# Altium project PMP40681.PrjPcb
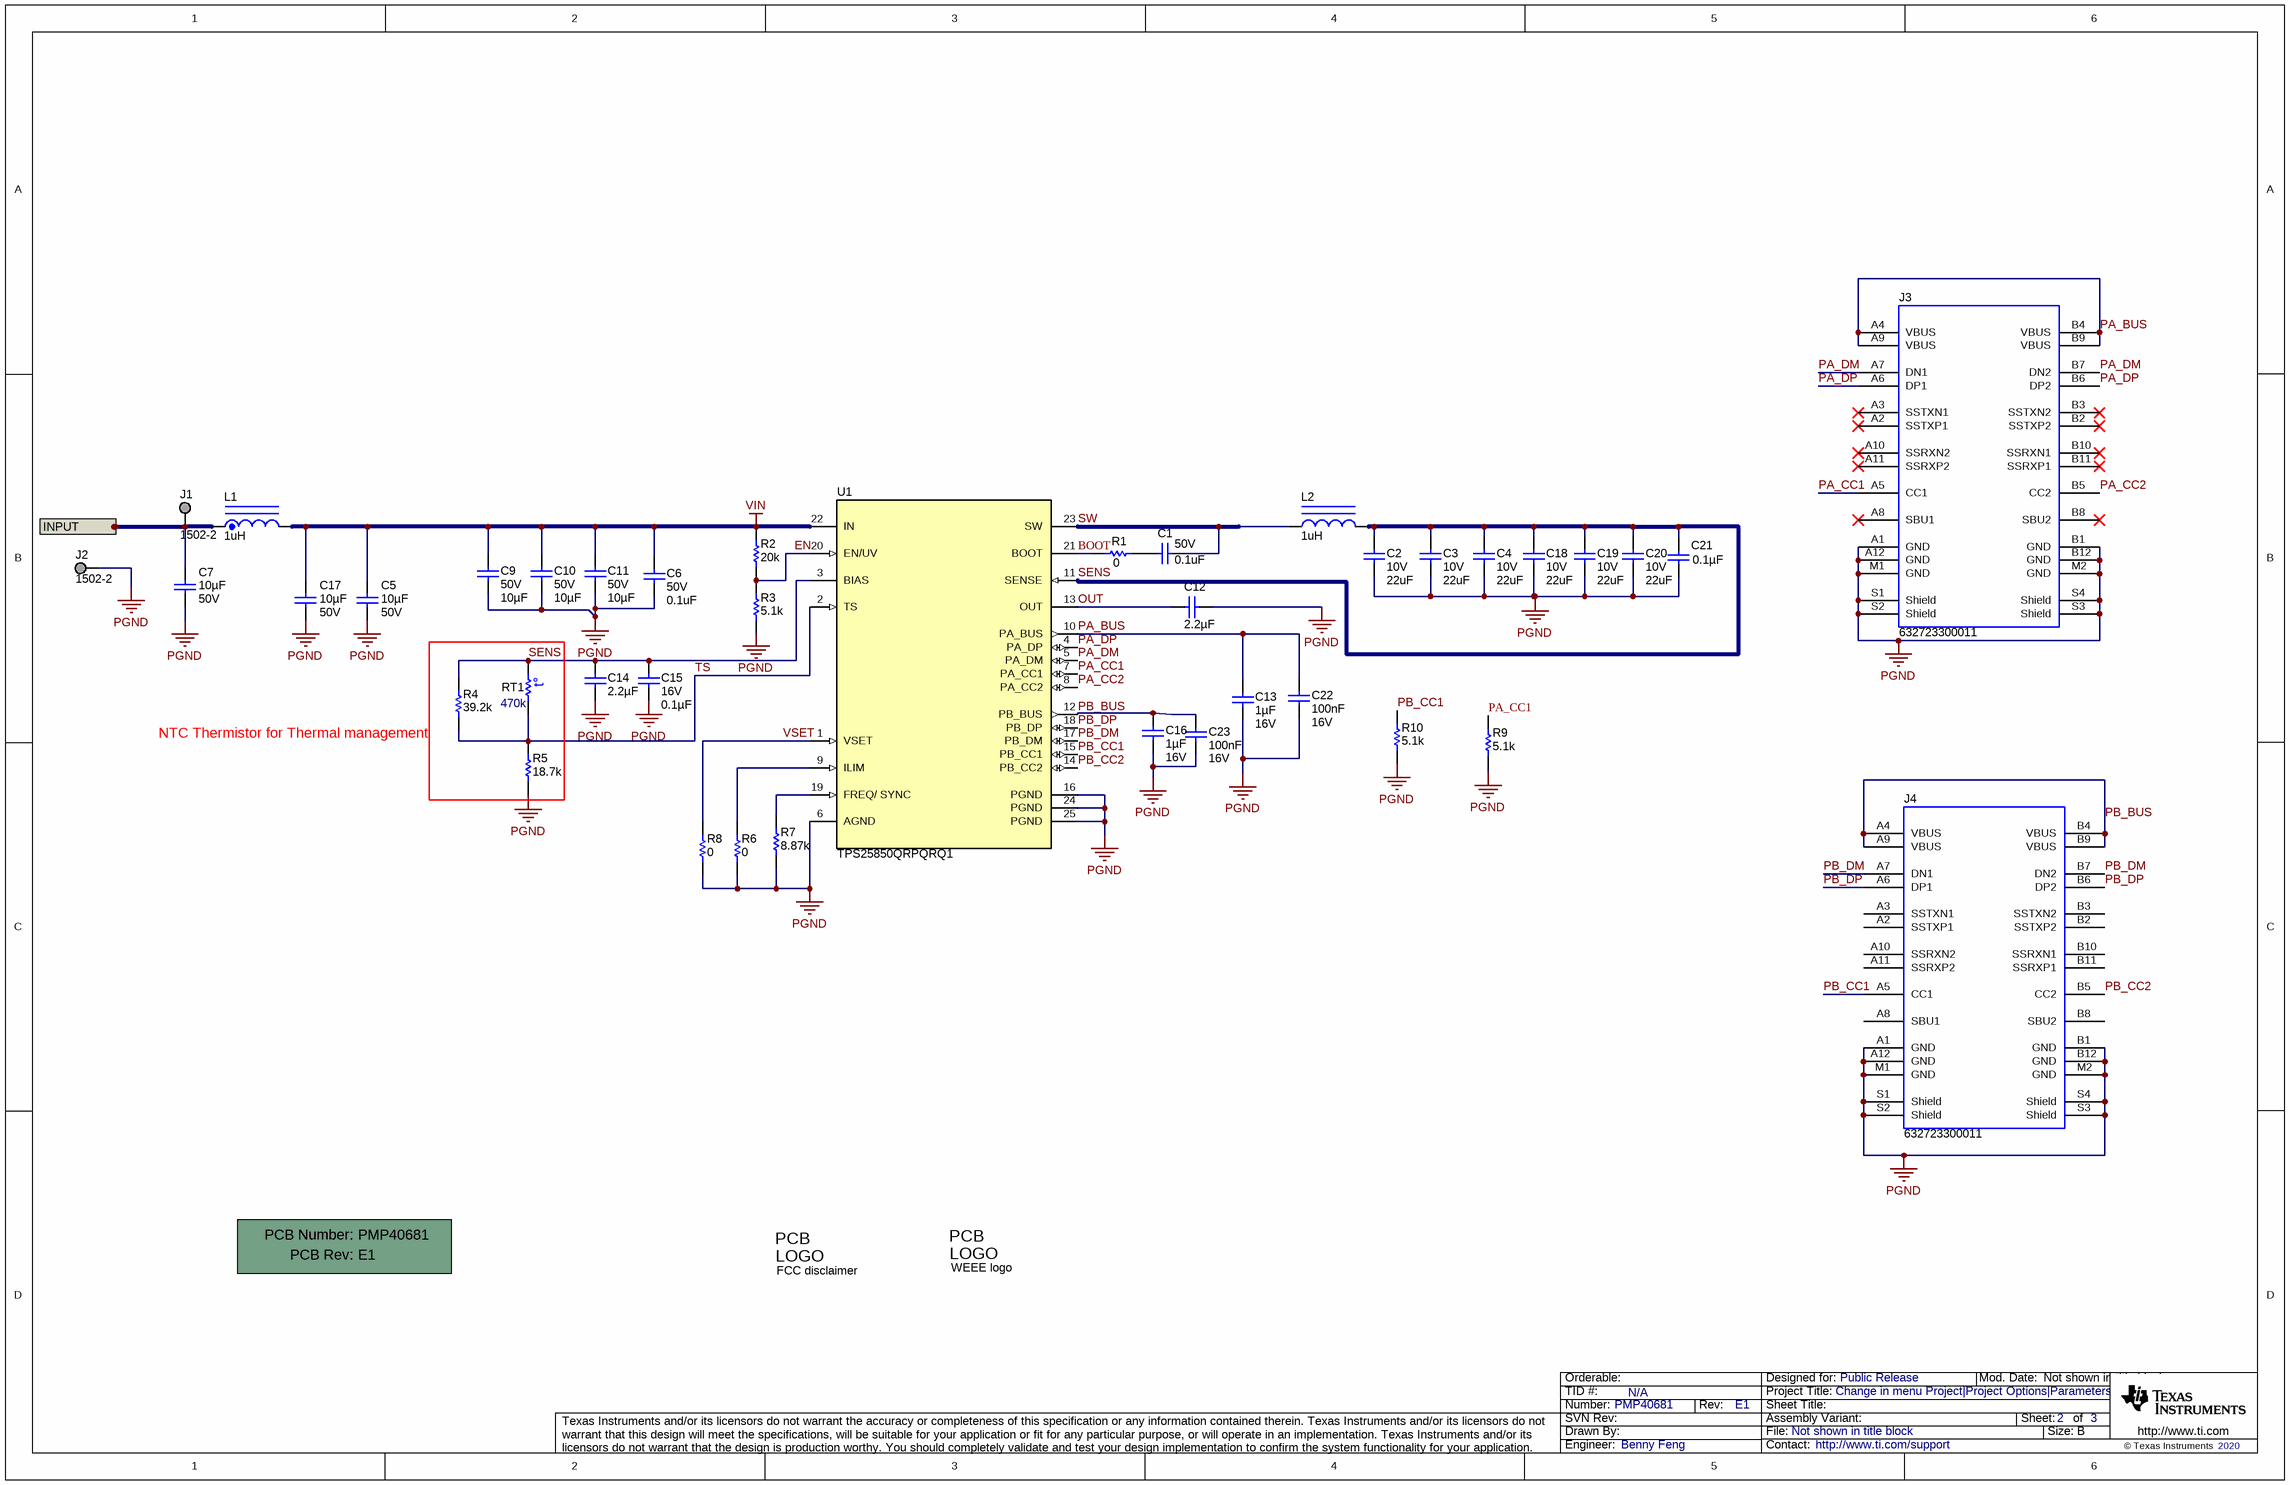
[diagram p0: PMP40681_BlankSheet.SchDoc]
CopyrightYear: 2020; PCB_Layout: Benny Feng; PCB_Rev: E1; PRJ_Customer: Public Release; PRJ_Engineer: Benny Feng; PRJ_Number: PMP40681; PRJ_Title: Change in menu Project|Project Options|Parameters; SCH_Rev: E1; TechSupport: http://www.ti.com/support; TID: N/A
1 sheet, 43 parts. Net scope: flat (ports and power ports of the same name join across sheets).
Board file: PMP40681_PCB.PcbDoc

## Sheet PMP40681_BlankSheet.SchDoc
size 431 x 279 mm; Date: Not shown in title block; ApprovedBy: Not shown in title block; CheckedBy: Not shown in title block; Author: Not shown in title block; CompanyName: Not shown in title block; Engineer: Not shown in title block; Organization: Not shown in title block; Address1: Not shown in title block; Address2: Not shown in title block; Address3: Not shown in title block; Address4: Not shown in title block; DocumentNumber: 2; Revision: Use project parameter SCH_Rev; SheetNumber: 2; SheetTotal: 3; PageSetup: Record=PageOptions¦CenterHorizontal=True¦CenterVertical=True¦PrintScale=1.00¦XCorrection=1.00¦YCorrection=1.00¦PrintKind=0¦BorderSize=5000000¦LeftOffset=0¦BottomOffset=0¦Orientation=2¦PaperLength=1000¦PaperWidth=1000¦Scale=100¦PaperSource=15¦PrintQuality=600¦MediaType=1¦DitherType=10¦PaperKind=Letter¦PrintScaleMode=1

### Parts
!PCB1  Printed Circuit Board  (value not drawn)  (mechanical)
C1  VDC_V: 50V  ValueDisplayed: 0.1uF  [0402]  (hidden comment: GCM155R71H104KE02D)
C2  VDC_V: 10V  ValueDisplayed: 22uF  [1206_180]  (hidden comment: GCM31CR71A226KE02)
C3  VDC_V: 10V  ValueDisplayed: 22uF  [1206_180]  (hidden comment: GCM31CR71A226KE02)
C4  VDC_V: 10V  ValueDisplayed: 22uF  [1206_180]  (hidden comment: GCM31CR71A226KE02)
C5  ValueDisplayed: 10µF  VDC_V: 50V  [1206_190]  (hidden comment: CGA5L1X7R1H106K160AC)
C6  VDC_V: 50V  ValueDisplayed: 0.1uF  [0402]  (hidden comment: GCM155R71H104KE02D)
C7  ValueDisplayed: 10µF  VDC_V: 50V  [1206_190]  (hidden comment: CGA5L1X7R1H106K160AC)
C9  VDC_V: 50V  ValueDisplayed: 10µF  [1206_190]  (hidden comment: CGA5L1X7R1H106K160AC)
C10  VDC_V: 50V  ValueDisplayed: 10µF  [1206_190]  (hidden comment: CGA5L1X7R1H106K160AC)
C11  VDC_V: 50V  ValueDisplayed: 10µF  [1206_190]  (hidden comment: CGA5L1X7R1H106K160AC)
C12  Cap_F: 2.2µF  [0603]  (hidden comment: GRM188R71A225KE15J)
C13  Cap_F: 1µF  VDC_V: 16V  [0603]  (hidden comment: GCM188R71C105KA64D)
C14  Cap_F: 2.2µF  [0603]  (hidden comment: GRM188R71A225KE15J)
C15  VDC_V: 16V  ValueDisplayed: 0.1µF  [0402]  (hidden comment: GCM155R71C104JA55D)
C16  Cap_F: 1µF  VDC_V: 16V  [0603]  (hidden comment: GCM188R71C105KA64D)
C17  ValueDisplayed: 10µF  VDC_V: 50V  [1206_190]  (hidden comment: CGA5L1X7R1H106K160AC)
C18  VDC_V: 10V  ValueDisplayed: 22uF  [1206_180]  (hidden comment: GCM31CR71A226KE02)
C19  VDC_V: 10V  ValueDisplayed: 22uF  [1206_180]  (hidden comment: GCM31CR71A226KE02)
C20  VDC_V: 10V  ValueDisplayed: 22uF  [1206_180]  (hidden comment: GCM31CR71A226KE02)
C21  ValueDisplayed: 0.1µF  [0603]  (hidden comment: C0603C104K5RACAUTO)
C22  Cap_F: 100nF  VDC_V: 16V  [0603]  (hidden comment: GCM188R71C104KA37J)
C23  Cap_F: 100nF  VDC_V: 16V  [0603]  (hidden comment: GCM188R71C104KA37J)
J1  1502-2  [Keystone1502-2]
J2  1502-2  [Keystone1502-2]
J3  632723300011  [Wurth_632_723_300_011]
J4  632723300011  [Wurth_632_723_300_011]
L1  ValueDisplayed: 1uH  [XAL4020]  (hidden comment: XAL4020-102MEB)
L2  ValueDisplayed: 1uH  [XAL8080]  (hidden comment: XAL8080-102MEB)
Logo1  FCC disclaimer  [FCC_disclaimer]  (no BOM)
Logo2  WEEE logo  [WEEE_Minimum]  (no BOM)
R1  ValueDisplayed: 0  [0402]  (hidden comment: CRCW04020000Z0ED)
R2  ValueDisplayed: 20k  [0402]  (hidden comment: CRCW040220K0JNED)
R3  ValueDisplayed: 5.1k  [0402]  (hidden comment: CRCW04025K10JNED)
R4  ValueDisplayed: 39.2k  [0402]  (hidden comment: CRCW040239K2FKED)
R5  ValueDisplayed: 18.7k  [0402]  (hidden comment: CRCW040218K7FKED)
R6  ValueDisplayed: 0  [0402]  (hidden comment: CRCW04020000Z0ED)
R7  ValueDisplayed: 8.87k  [0402]  (hidden comment: CRCW04028K87FKED)
R8  ValueDisplayed: 0  [0402]  (hidden comment: CRCW04020000Z0ED)
R9  ValueDisplayed: 5.1k  [0402]  (hidden comment: CRCW04025K10JNED)
R10  ValueDisplayed: 5.1k  [0402]  (hidden comment: CRCW04025K10JNED)
RT1  value 470k  [0402S]  (hidden comment: NCP15WM474J03RC)
U1  TPS25850QRPQRQ1  [RPQ0025A]

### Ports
INPUT (in)

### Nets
PGND: C2.2 C3.2 C4.2 C5.2 C6.2 C7.2 C9.2 C10.2 C11.2 C12.2 C13.2 C14.2 C15.2 C16.2 C17.2 C18.2 C19.2 C20.2 C21.2 C22.2 C23.2 J2.1 J3.A1(GND) J3.A12(GND) J3.B1(GND) J3.B12(GND) J3.M1(GND) J3.M2(GND) J3.S1(Shield) J3.S2(Shield) J3.S3(Shield) J3.S4(Shield) J4.A1(GND) J4.A12(GND) J4.B1(GND) J4.B12(GND) J4.M1(GND) J4.M2(GND) J4.S1(Shield) J4.S2(Shield) J4.S3(Shield) J4.S4(Shield) R3.1 R5.1 R6.2 R7.1 R8.2 R9.1 R10.1 U1.6(AGND) U1.16(PGND) U1.24(PGND) U1.25(PGND)
VIN: C5.1 C6.1 C9.1 C10.1 C11.1 C17.1 L1.2 R2.2 U1.22(IN)
BOOT: R1.1 U1.21(BOOT)
EN: R2.1 R3.2 U1.20(EN/UV)
INPUT: C7.1 J1.1 L1.1 ; port INPUT
OUT: C12.1 U1.13(OUT)
PA_BUS: C13.1 C22.1 J3.A4(VBUS) J3.A9(VBUS) J3.B4(VBUS) J3.B9(VBUS) U1.10(PA_BUS)
PA_CC1: J3.A5(CC1) R9.2 U1.7(PA_CC1)
PA_CC2: J3.B5(CC2) U1.8(PA_CC2)
PA_DM: J3.A7(DN1) J3.B7(DN2) U1.5(PA_DM)
PA_DP: J3.A6(DP1) J3.B6(DP2) U1.4(PA_DP)
PB_BUS: C16.1 C23.1 J4.A4(VBUS) J4.A9(VBUS) J4.B4(VBUS) J4.B9(VBUS) U1.12(PB_BUS)
PB_CC1: J4.A5(CC1) R10.2 U1.15(PB_CC1)
PB_CC2: J4.B5(CC2) U1.14(PB_CC2)
PB_DM: J4.A7(DN1) J4.B7(DN2) U1.17(PB_DM)
PB_DP: J4.A6(DP1) J4.B6(DP2) U1.18(PB_DP)
SENS: C2.1 C3.1 C4.1 C14.1 C15.1 C18.1 C19.1 C20.1 C21.1 L2.2 R4.2 RT1.2 U1.3(BIAS) U1.11(SENSE)
SW: C1.1 L2.1 U1.23(SW)
TS: R4.1 R5.2 RT1.1 U1.2(TS)
VSET: R8.1 U1.1(VSET)
NetC1_2: C1.2 R1.2
NetR6_1: R6.1 U1.9(ILIM)
NetR7_2: R7.2 U1.19(FREQ/_SYNC)

Not connected (* = marked no-connect by the designer): J3 A2(SSTXP1)* A3(SSTXN1)* A8(SBU1)* A10(SSRXN2)* A11(SSRXP2)* B2(SSTXP2)* B3(SSTXN2)* B8(SBU2)* B10(SSRXN1)* B11(SSRXP1)*; J4 A2(SSTXP1) A3(SSTXN1) A8(SBU1) A10(SSRXN2) A11(SSRXP2) B2(SSTXP2) B3(SSTXN2) B8(SBU2) B10(SSRXN1) B11(SSRXP1)

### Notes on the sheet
- (near R4) NTC Thermistor for Thermal management
- Labels drawn without touching a wire or pin: FREQ, ILIM

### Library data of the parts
!PCB1 = CMP-0003618-2: Manufacturer: Any; PartNumber: PMP40681
C1 = CMP-0006356-1: CAP, CERM, 0.1 uF, 50 V, +/- 10%, X7R, AEC-Q200 Grade 1, 0402; Manufacturer: MuRata; TaMin_C: -55°C; Polarized: N; SizeAreaWB_mm2: 3; U/M: EA; Value: 0.1uF; TaMax_C: 125°C; SizeZ_mm: 0.6; SizeX_mm: 1; SizeY_mm: 0.5; AEC Qualified: Y; Cap_F: 100nF; AEC Category: Q200; Value1: Unknown
C2-C4 C18-C20 = CMP-0008811-1: CAP, CERM, 22 uF, 10 V, +/- 10%, X7R, AEC-Q200 Grade 1, 1206; Manufacturer: MuRata; TaMin_C: -55°C; Polarized: N; SizeAreaWB_mm2: 10.92; Value1: Unknown; U/M: EA; Value: 22uF; TaMax_C: 125°C; SizeZ_mm: 1.8; SizeX_mm: 3.2; SizeY_mm: 1.6; Cap_Case: 1206; SizeArea_mm2: 5.12; AEC Qualified: Y; Cap_F: 22µF; AEC Category: Q200; AEC Grade: 1
C5 C7 C17 = CMP-0085950-1: CAP, CERM, 10 µF, 50 V,+/- 10%, X7R, AEC-Q200 Grade 1, 1206; Manufacturer: TDK; SizeZ_mm: 1.9; Value: 10uF; Cap_Case: 1206; AEC Grade: 1; TaMin_C: -55°C; U/M: EA; SizeArea_mm2: 5.12; TaMax_C: 125°C; AEC Qualified: Y; AEC Category: Q200; SizeX_mm: 3.2; SizeY_mm: 1.6; Polarized: N; SizeAreaWB_mm2: 10.92
C6 = CMP-0006356-2: CAP, CERM, 0.1 uF, 50 V, +/- 10%, X7R, AEC-Q200 Grade 1, 0402; Manufacturer: MuRata; TaMin_C: -55°C; Polarized: N; SizeAreaWB_mm2: 3; Value1: Unknown; U/M: EA; Value: 0.1uF; TaMax_C: 125°C; SizeZ_mm: 0.6; SizeX_mm: 1; SizeY_mm: 0.5; AEC Qualified: Y; Cap_F: 100nF; AEC Category: Q200
C9-C11 = CMP-0085950-1: CAP, CERM, 10 µF, 50 V,+/- 10%, X7R, AEC-Q200 Grade 1, 1206; Manufacturer: TDK; TaMin_C: -55°C; Polarized: N; SizeAreaWB_mm2: 10.92; U/M: EA; Value: 10uF; TaMax_C: 125°C; SizeZ_mm: 1.9; SizeX_mm: 3.2; SizeY_mm: 1.6; Cap_Case: 1206; SizeArea_mm2: 5.12; AEC Qualified: Y; AEC Grade: 1; AEC Category: Q200
C12 C14 = CMP-0084284-1: CAP, CERM, 2.2 µF, 10 V,+/- 10%, X7R, AEC-Q200 Grade 1, 0603; Manufacturer: MuRata; TaMin_C: -55°C; Polarized: N; SizeAreaWB_mm2: 4.68; U/M: EA; Value: 2.2uF; TaMax_C: 125°C; SizeZ_mm: 1; SizeX_mm: 1.6; SizeY_mm: 0.8; Value2: 10V; SizeArea_mm2: 1.28; AEC Qualified: Y; AEC Category: Q200
C13 C16 = CMP-0007136-3: CAP, CERM, 1 uF, 16 V, +/- 10%, X7R, AEC-Q200 Grade 1, 0603; Manufacturer: MuRata; TaMin_C: -55°C; Polarized: N; SizeAreaWB_mm2: 4.68; Value1: Unknown; U/M: EA; Value: 1uF; TaMax_C: 125°C; SizeZ_mm: 1; SizeX_mm: 1.6; SizeY_mm: 0.8; SizeArea_mm2: 1.28; AEC Qualified: Y; AEC Category: Q200
C15 = CMP-0080702-1: CAP, CERM, 0.1 µF, 16 V,+/- 5%, X7R, AEC-Q200 Grade 1, 0402; Manufacturer: MuRata; TaMin_C: -55°C; Polarized: N; SizeAreaWB_mm2: 3; U/M: EA; Value: 0.1uF; TaMax_C: 125°C; SizeZ_mm: 0.6; SizeX_mm: 1; SizeY_mm: 0.5; AEC Qualified: Y; Cap_F: 100nF; AEC Category: Q200
C21 = CMP-0079602-1: CAP, CERM, 0.1 µF, 50 V,+/- 10%, X7R, AEC-Q200 Grade 1, 0603; Manufacturer: Kemet; TaMin_C: -55°C; Polarized: N; SizeAreaWB_mm2: 4.68; U/M: EA; Value: 0.1uF; TaMax_C: 125°C; SizeZ_mm: 1; SizeX_mm: 1.6; SizeY_mm: 0.8; Value2: 50V; SizeArea_mm2: 1.28; CompType: Capacitor; AEC Qualified: Y; Cap_F: 100nF; AEC Category: Q200
C22 C23 = CMP-0007135-3: CAP, CERM, 0.1 uF, 16 V, +/- 10%, X7R, AEC-Q200 Grade 1, 0603; Manufacturer: MuRata; TaMin_C: -55°C; Polarized: N; SizeAreaWB_mm2: 4.68; U/M: EA; Value: 0.1uF; TaMax_C: 125°C; SizeZ_mm: 1; SizeX_mm: 1.6; SizeY_mm: 0.8; SizeArea_mm2: 1.28; AEC Qualified: Y; AEC Category: Q200; Value1: Unknown
J1 J2 = CMP-0055113-1: Terminal, Turret, TH, Double; Manufacturer: Keystone; CT: FALSE; Green_REACh: Passed; CompType: Turret Terminal; Green_Lifecycle: Active
J3 J4 = CMP-0080891-1: Connector, Receptacle, USB Type C, R/A; Manufacturer: Wurth Elektronik; Current_A: 3A; Gender: Female; Voltage_V: 5V; ContactFinish: Gold; Cert_UL: Y
L1 = CMP-0060983-2: Inductor, Shielded, Composite, 1 µH, 8.75 A, 0.01 ohm, AEC-Q200 Grade 1, SMD; Manufacturer: Coilcraft; SizeY_mm: 4.3; Green_REACh: Incomplete; Irms: 9.6A @ 40C rise; Green_Lifecycle: Not Set; Value: 1uH; AEC Category: Q200; SizeZ_mm: 2.1; DCR_ohm: 0.01; AEC Qualified: Y; SizeArea_mm2: 18.49; Value2: 8.75A; Isat: 8.75A @ 30% inductance drop; Ind_H: 1µH; AEC Grade: 1; SizeAreaWB_mm2: 28.09
L2 = CMP-0061059-1: Inductor, Shielded, Composite, 1 uH, 31.38 A, 0.0021 ohm, SMD; Manufacturer: Coilcraft; Isat: 31.38A @ 30% inductance drop; Irms: 34.1A @ 40C rise; Green_Lifecycle: Not Set; SizeAreaWB_mm2: 107.06; DCR_ohm: 2.1m; Green_REACh: Incomplete; Value: 1uH; Imax_A: 31.38A; SizeZ_mm: 8; SizeX_mm: 8.1; SizeY_mm: 8.6; SizeArea_mm2: 69.66; Ind_H: 1µH; AEC Qualified: N; AEC Category: Q200
Logo1 = CMP-0074847-1: FCC_disclaimer; Library Reference: Logo
Logo2 = CMP-0074769-1
R1 R8 = CMP-0026822-3: RES, 0, 5%, 0.063 W, AEC-Q200 Grade 0, 0402; Manufacturer: Vishay-Dale; Power_W: 63mW; TempCo: 200 ppm/C; Value_Code: 0000; Value: 0; SizeX_mm: 1; SizeY_mm: 0.5; SizeZ_mm: 0.6; Value2: 0.063W; AEC Qualified: Y; AEC Category: Q200; EIA_Code: E24; VDC_V: 50V
R2 = CMP-0026875-3: RES, 20 k, 5%, 0.063 W, AEC-Q200 Grade 0, 0402; Manufacturer: Vishay-Dale; Power_W: 63mW; TempCo: 200 ppm/C; Value_Code: 20k0; Value: 20k; EIA_Code: E24; SizeX_mm: 1; SizeY_mm: 0.5; SizeZ_mm: 0.6; Value2: 0.063W; AEC Qualified: Y; VDC_V: 50V; AEC Category: Q200; AEC Grade: 0
R3 = CMP-0026951-5: RES, 5.1 k, 5%, 0.063 W, AEC-Q200 Grade 0, 0402; Manufacturer: Vishay-Dale; Power_W: 63mW; TempCo: 200 ppm/C; Value_Code: 5k10; Value: 5.1k; SizeX_mm: 1; SizeY_mm: 0.5; SizeZ_mm: 0.6; Value2: 0.063W; AEC Qualified: Y; VDC_V: 50V; AEC Category: Q200; AEC Grade: 0; EIA_Code: E24
R4 = CMP-0026327-2: RES, 39.2 k, 1%, 0.063 W, AEC-Q200 Grade 0, 0402; Manufacturer: Vishay-Dale; Power_W: 63mW; TempCo: 100 ppm/C; Value_Code: 39k2; Value: 39.2k; EIA_Code: E96; SizeX_mm: 1; SizeY_mm: 0.5; SizeZ_mm: 0.6; Value2: 0.063W; AEC Qualified: Y; VDC_V: 50V; AEC Category: Q200; AEC Grade: 0
R5 = CMP-0026060-3: RES, 18.7 k, 1%, 0.063 W, AEC-Q200 Grade 0, 0402; Manufacturer: Vishay-Dale; Power_W: 63mW; TempCo: 100 ppm/C; Value_Code: 18k7; Value: 18.7k; EIA_Code: E96; SizeX_mm: 1; SizeY_mm: 0.5; SizeZ_mm: 0.6; Value2: 0.063W; AEC Qualified: Y; VDC_V: 50V; AEC Category: Q200; AEC Grade: 0
R6 = CMP-0026822-3: RES, 0, 5%, 0.063 W, AEC-Q200 Grade 0, 0402; Manufacturer: Vishay-Dale; Power_W: 63mW; TempCo: 200 ppm/C; Value_Code: 0000; Value: 0; EIA_Code: E24; SizeX_mm: 1; SizeY_mm: 0.5; SizeZ_mm: 0.6; Value2: 0.063W; AEC Qualified: Y; VDC_V: 50V; AEC Category: Q200
R7 = CMP-0026592-2: RES, 8.87 k, 1%, 0.063 W, AEC-Q200 Grade 0, 0402; Manufacturer: Vishay-Dale; Power_W: 63mW; TempCo: 100 ppm/C; Value_Code: 8k87; Value: 8.87k; EIA_Code: E96; SizeX_mm: 1; SizeY_mm: 0.5; SizeZ_mm: 0.6; Value2: 0.063W; AEC Qualified: Y; VDC_V: 50V; AEC Category: Q200; AEC Grade: 0
R9 R10 = CMP-0026951-5: RES, 5.1 k, 5%, 0.063 W, AEC-Q200 Grade 0, 0402; Manufacturer: Vishay-Dale; Power_W: 63mW; TempCo: 200 ppm/C; Value_Code: 5k10; Value: 5.1k; EIA_Code: E24; SizeX_mm: 1; SizeY_mm: 0.5; SizeZ_mm: 0.6; Value2: 0.063W; AEC Qualified: Y; VDC_V: 50V; AEC Category: Q200; AEC Grade: 0
RT1 = CMP-0002542-1: Thermistor NTC, 470k ohm, 5%, 0402; Manufacturer: MuRata; TaMax_C: 125°C; SizeX_mm: 1; SizeY_mm: 0.5; TaMin_C: -40°C; Power_W: 100mW; SizeZ_mm: 0.6; SizeAreaWB_mm2: 3; U/M: EA
U1 = CMP-0860365-2: Dual 3A USB Type-C Charging Ports Controller with Programmable Current Limit and Thermal Management, RPQ0025A (VQFN-25); Alternate Manufacturer: Texas Instruments; SizeZ_mm: 1; SizeX_mm: 3.5; AEC Category: Q200; CompType: IC; SizeY_mm: 4.5; SizeArea_mm2: 15.75; AEC Qualified: Y; SizeAreaWB_mm2: 24.75

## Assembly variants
001: not fitted C19 C20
